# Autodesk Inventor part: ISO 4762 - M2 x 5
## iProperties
Created: 2008-01
Part Number: ISO 4762 - M2 x 5
Material: Stainless Steel, 440C
Description: Hexagon Socket Head Cap Screw
Document SubType Name: Modeling
Standard: ISO 4762
Designer: latalom
Standard Revision: Fourth edition 2004-03-01
Standards Organization: ISO
Language: en-US
Size Designation: M2 x 5
Categories: <MemberInstance><Categories><Category DisplayName="Fasteners" InternalName="e4da775c-781d-43d5-af7c-5136215cf5a6" Mnemonic="FSTN"><Category DisplayName="Bolts"
Density: 7.75 g/cm^3
IsCustomPart: 0
Author: latalom
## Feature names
1. Body [Revolution]
2. Slot [Extrusion]
3. Fillet1
4. Chamfer1
5. Fillet2
